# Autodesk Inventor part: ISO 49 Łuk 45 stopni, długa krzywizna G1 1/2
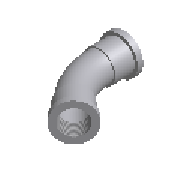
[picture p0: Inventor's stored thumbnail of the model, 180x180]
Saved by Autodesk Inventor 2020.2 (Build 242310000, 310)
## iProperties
Manager: www.cadconsulting.pl
Company: Fabian Stasiak CAD Consulting
Created: 2014-02
Part Number: ISO 49 Łuk 45 stopni, długa krzywizna G1 1/2
Material: Żelazo, ciągliwe
Description: Elementy z żeliwa ciągliwego - Łuk 45° z długą krzywizną G1
Document SubType Name: Modeling
Standard: ISO 49
Designer: F.Stasiak
Standard Revision: Second edition 1994-12-15
Standards Organization: ISO
Language: pl-PL
Size Designation: 1/2
Categories: <MemberInstance><Categories><Category DisplayName="Rury cienko- i grubościenne" InternalName="4347fa0f-2144-441d-94cd-e3e15c92b736" Mnemonic="TUBEANDPIPE"><Cate
Density: 7.15 g/cm^3
Appearance: Częściowo polerowana
Catalog Web Link: www.expertbooks.pl
IsCustomPart: 0
NAME: PIPING: ISO 49 45 Deg Long Sweep Bend G1
DATA: <meta><inlinegroups number="0" deflen="0"></inlinegroups><connections number="2"></connections><angles><a>2.35619449019234</a></angles></meta>
Author: F.Stasiak
Subject: Zbiór ćwiczeń. Autodesk Inventor 2020. Kurs Professional
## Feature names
1. Revolution1
2. Revolution2
3. Sweep1
## Parameters: a = 36 mm, MD = 18.631 mm, H = 28.21 mm, d0 = 18.631 mm, d1 = 28.21 mm, d2 = 4.34 mm, d3 = 19.5 mm, d4 = 0.3124 mm, d26 = 90 deg, d5 = 18.631 mm, d6 = 23.87 mm, d7 = 28.21 mm, d8 = 4.34 mm, d9 = 19.5 mm, d10 = 0.3124 mm, d37 = 90 deg, EE = 4.34 mm, D = 21.7 mm, z = 23 mm, d11 = 23.87 mm, d12 = 0, d83 = 25.4 mm, d84 = 0, d85 = 25.4 mm, d86 = 0, d13 = 13 mm, d14 = 21.7 mm, d15 = 36 mm, d16 = 45 deg, d17 = 36 mm, d18 = 13 mm, d99 = 0, Size_Designation = 5 mm
